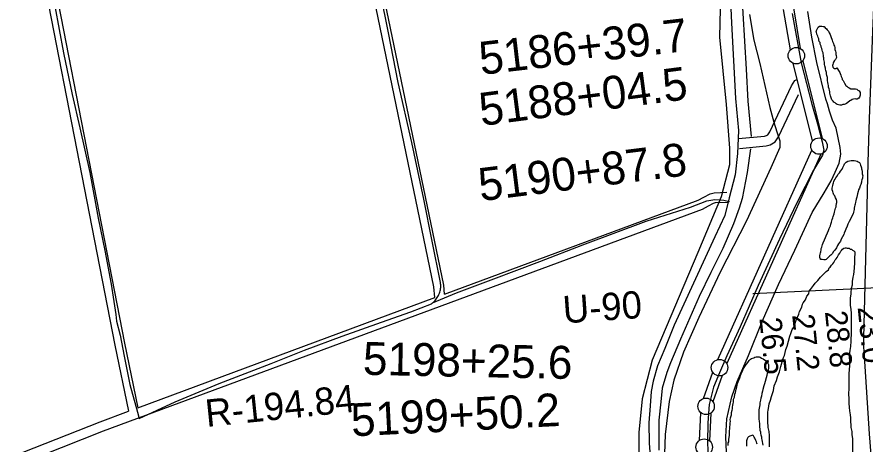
# Model space of a CAD drawing. Extents: x 3324125 to 3362000, y 600753 to 626151.
# Drawn here: x 3330131 to 3332706, y 616943 to 618241 of the extents above; entities that cross this region are included whole.
import ezdxf

# ---------------------------------------------------------------- set-up
doc = ezdxf.new("R2010")
doc.units = 0
for name, color, linetype in [('V-DTCH-CNTR', 7, 'Continuous'), ('V-FLOD-BASE', 7, 'Continuous'), ('V-LEVE-TOET', 7, 'Continuous'), ('V-RIVR-RANG', 7, 'Continuous'), ('V-RIVR-RANG-IDEN', 7, 'Continuous'), ('V-ROAD-CNTR', 7, 'Continuous'), ('V-SITE-VEGE', 7, 'Continuous'), ('V-SURV-IDEN', 7, 'Continuous'), ('V-SURV-LINE', 7, 'Continuous'), ('V-TOPO-MAJR', 7, 'Continuous'), ('V-TOPO-SHOR', 7, 'Continuous')]:
    doc.layers.add(name, color=color, linetype=linetype)

msp = doc.modelspace()

# ---------------------------------------------------------------- linework, layer by layer
at = {"layer": 'V-DTCH-CNTR'}
for points in [[(3330126.9, 618919.7), (3330132.5, 618888.2), (3330139.8, 618849.5), (3330156.8, 618763.4), (3330171.7, 618671.3), (3330189.8, 618572.8), (3330210.7, 618476.7), (3330226.4, 618377.8), (3330245.6, 618273.4), (3330271.8, 618131.8), (3330298.4, 618004.6), (3330321.7, 617904.1), (3330351.9, 617768.1), (3330376.9, 617628.9), (3330397.7, 617531.6), (3330416.6, 617429.1), (3330430.7, 617337.1), (3330433, 617316.3), (3330443.5, 617274), (3330455.8, 617210.2), (3330473.6, 617123.7), (3330496.5, 617039.5), (3330502, 617020.8)], [(3330502, 617020.8), (3330611.4, 617071.8), (3330744.8, 617126.7), (3330902.1, 617187.8), (3331003.5, 617227.8), (3331118.5, 617270.9), (3331237.5, 617313.1), (3331326.1, 617345.2), (3331389.2, 617369.5), (3331392.1, 617371.7), (3331394.9, 617374.1), (3331397.6, 617376.6), (3331400.1, 617379.3), (3331402.5, 617382.1), (3331404.8, 617385), (3331406.8, 617388), (3331408.7, 617391.2), (3331410.4, 617394.4), (3331412, 617397.8), (3331413.3, 617401.2), (3331414.5, 617404.7), (3331415.4, 617408.2), (3331416.2, 617411.8), (3331416.8, 617415.5), (3331417.2, 617419.1), (3331417.3, 617422.8), (3331417.3, 617426.5), (3331417, 617430.2), (3331416.6, 617433.8), (3331391.2, 617559.1), (3331366.5, 617686.7), (3331329.4, 617859.7), (3331288.4, 618041.6), (3331258.3, 618192.4), (3331234.4, 618313.6)], [(3331392.1, 617371.7), (3331464.8, 617402.3), (3331578.2, 617445.4), (3331717.9, 617497.8), (3331848.9, 617548.8), (3332041.3, 617620), (3332175.4, 617663), (3332225.7, 617682.5), (3332249.6, 617686.4), (3332277.5, 617683.8), (3332293.9, 617680.2)]]:
    msp.add_lwpolyline(points, dxfattribs=at)
at = {"layer": 'V-FLOD-BASE'}
msp.add_lwpolyline([(3332485, 618250.7), (3332512, 618101.1), (3332544.5, 617976), (3332561.6, 617915.8), (3332575.8, 617860.9), (3332580.3, 617836.3), (3332576.7, 617820.6), (3332549, 617774.7), (3332498.2, 617675.8), (3332446.1, 617565.8), (3332381, 617424.5), (3332326.5, 617298.8), (3332285.7, 617210.9), (3332264.3, 617159.1), (3332246, 617115.5), (3332232.8, 617063), (3332228.4, 617007.6), (3332227.4, 616947.5), (3332230.4, 616875.1)], dxfattribs=at)
at = {"layer": 'V-LEVE-TOET'}
for points in [[(3332355.4, 618248), (3332368.3, 618169.8), (3332386.5, 618099), (3332416.6, 617965.8), (3332428.6, 617920.8), (3332438.3, 617891.5), (3332446.9, 617864), (3332447.3, 617844.2), (3332419.5, 617781.9), (3332345.5, 617621.4), (3332265.7, 617464.9), (3332200.7, 617327.6), (3332155, 617221.7), (3332125.3, 617136.7), (3332110.9, 617072), (3332098.6, 616972.3), (3332097, 616912.8)], [(3332286, 616894.6), (3332282.9, 616965.2), (3332285.6, 617019.5), (3332301.2, 617086.5), (3332317.3, 617133.1), (3332352.2, 617212.2), (3332393.7, 617315.8), (3332442.9, 617428.1), (3332492.6, 617532.3), (3332545.3, 617646.3), (3332581.8, 617706.2), (3332602.5, 617742.8), (3332615.5, 617769), (3332626.8, 617796.4), (3332632.2, 617823.7), (3332630.6, 617844.2), (3332618.1, 617902.6), (3332606.6, 617926.6), (3332597.4, 617954.7), (3332591.8, 617976.9), (3332587.2, 617990.4), (3332559.9, 618102), (3332544.6, 618179.1), (3332532.3, 618256.8)]]:
    msp.add_lwpolyline(points, dxfattribs=at)
at = {"layer": 'V-RIVR-RANG'}
msp.add_line((3332364.6, 617400.2), (3333505.2, 617456.3), dxfattribs=at)
at = {"layer": 'V-ROAD-CNTR'}
for points in [[(3332435.8, 620389.6), (3332374.7, 619523.7), (3332301.3, 618552.7), (3332296.7, 618455.5), (3332294.2, 618354.6), (3332300.5, 618222.7), (3332312.6, 617992.5), (3332321.2, 617895.8), (3332318.6, 617826.1), (3332311.6, 617761.4), (3332293.4, 617690.8), (3332279.8, 617637.3), (3332250, 617572.9), (3332125.9, 617304.4), (3332097.6, 617233.7), (3332075.6, 617180.9), (3332062.2, 617134.3), (3332055.9, 617103.1), (3332053.1, 617059.6), (3332049, 617007.9), (3332050.3, 616945.8), (3332056, 616867)], [(3330111, 618871.3), (3330427.3, 617243.1), (3330469.2, 617043)], [(3330140.4, 618877), (3330456.7, 617249.1), (3330497.7, 617053.5)], [(3331399.7, 617387.8), (3331396.8, 617421), (3331161.7, 618557), (3331116.3, 618749.3)], [(3331428.8, 617398.6), (3331426.5, 617425.3), (3331220.1, 618422.6)], [(3332321.9, 617871), (3332400.7, 617878.7), (3332406.2, 617880), (3332410.9, 617883), (3332416.3, 617891.4), (3332482.7, 618031.4), (3332492.6, 618047.7), (3332498.7, 618050.4)], [(3332324.9, 617841.1), (3332405.7, 617849), (3332418, 617852), (3332432.6, 617861.1), (3332442.6, 617876.8), (3332503.3, 618004.8)], [(3331428.8, 617398.6), (3332199.2, 617684), (3332215.9, 617693.5), (3332235.5, 617703.7), (3332248.1, 617706.4), (3332286.4, 617708.2)], [(3329622.7, 616703.3), (3329633, 616708.7), (3329640.7, 616710), (3329667.1, 616715.1), (3329709.7, 616718.1), (3329737.4, 616721.6), (3329760, 616732.4), (3330393.7, 616983), (3332211.8, 617656.7), (3332230.2, 617667.1), (3332245.9, 617675.2), (3332252, 617676.6), (3332287.8, 617678.2)], [(3330497.7, 617053.5), (3331399.7, 617387.8)], [(3329608.8, 616729.9), (3329623.3, 616737.5), (3329635.4, 616739.5), (3329663.2, 616744.9), (3329706.7, 616747.9), (3329728.8, 616750.8), (3329748, 616759.9), (3330382.9, 617011), (3330469.2, 617043)]]:
    msp.add_lwpolyline(points, dxfattribs=at)
at = {"layer": 'V-SITE-VEGE'}
for points in [[(3332415.4, 616934.8), (3332415.6, 616969.1), (3332414.3, 616981.5), (3332411.7, 616993.8), (3332411.7, 616997.9), (3332410.4, 617007.6), (3332410.6, 617040.5), (3332412, 617044.6), (3332413.4, 617058.3), (3332414.9, 617065.1), (3332419, 617076.1), (3332421.9, 617087), (3332427.5, 617106.2), (3332430.3, 617119.9), (3332437.3, 617136.3), (3332440.1, 617147.3), (3332445.7, 617162.3), (3332449.9, 617178.8), (3332454.1, 617192.5), (3332458.3, 617206.1), (3332461.1, 617211.6), (3332465.3, 617230.8), (3332469.5, 617240.4), (3332473.7, 617255.4), (3332477.9, 617270.5), (3332480.7, 617278.7), (3332484.9, 617291), (3332489.1, 617297.8), (3332494.6, 617312.9), (3332497.4, 617322.5), (3332504.4, 617337.5), (3332507.2, 617345.7), (3332514.1, 617359.4), (3332515.6, 617367.6), (3332518.3, 617371.7), (3332525.3, 617381.3), (3332529.4, 617392.2), (3332535, 617399.1), (3332536.4, 617407.3), (3332540.6, 617412.7), (3332548.9, 617425), (3332554.4, 617431.8), (3332562.7, 617440), (3332571, 617449.6), (3332575.1, 617455), (3332587.5, 617467.3), (3332594.4, 617472.7), (3332597.2, 617478.2), (3332600, 617480.9), (3332604.1, 617486.4), (3332608.3, 617490.5), (3332611, 617494.6), (3332615.2, 617502.8), (3332618, 617505.5), (3332620.7, 617509.6), (3332624.9, 617517.8), (3332629.1, 617523.3), (3332631.8, 617528.7), (3332634.6, 617531.5), (3332637.4, 617535.6), (3332641.5, 617538.3), (3332645.6, 617539.6)], [(3332645.6, 617539.6), (3332648.4, 617539.6), (3332651.1, 617538.2), (3332658, 617538.2), (3332660.7, 617535.4), (3332664.8, 617535.4), (3332667.5, 617532.6), (3332671.6, 617529.9), (3332674.3, 617527.1), (3332674.2, 617503.8), (3332674.1, 617494.2), (3332672.7, 617477.7), (3332671.2, 617458.5), (3332668.4, 617450.3), (3332666.9, 617436.6), (3332666.8, 617425.6), (3332664, 617416.1), (3332662.6, 617403.7), (3332662.6, 617399.6), (3332661.1, 617385.9), (3332661, 617365.3), (3332662.2, 617351.6), (3332663.5, 617340.6), (3332663.2, 617283), (3332663, 617255.6), (3332661.5, 617239.1), (3332660.1, 617226.8), (3332657.2, 617211.7), (3332658.5, 617189.8), (3332658.4, 617181.5), (3332656.9, 617156.8), (3332656.6, 617121.2), (3332656.6, 617110.2), (3332655.1, 617097.9), (3332656.4, 617078.7), (3332656.3, 617067.7), (3332657.6, 617054), (3332658.9, 617044.4), (3332660.2, 617032), (3332661.5, 617022.4), (3332661.4, 617010.1), (3332662.7, 617001.8), (3332662.7, 616993.6), (3332665.3, 616981.2), (3332665.3, 616971.6), (3332667.9, 616959.3), (3332667.6, 616908.5)]]:
    msp.add_lwpolyline(points, dxfattribs=at)
at = {"layer": 'V-SURV-LINE'}
for points in [[(3332488.1, 618268.5), (3332508.7, 618145.3)], [(3332479.1, 618140.3), (3332458.5, 618263.5)], [(3332546.6, 617864), (3332487.5, 618100.1)], [(3332516.6, 618107.3), (3332575.7, 617871.3)], [(3332258.5, 617199.6), (3332544.2, 617836.2)], [(3332571.6, 617823.9), (3332285.9, 617187.3)], [(3332215.5, 617081.4), (3332243.3, 617161.3)], [(3332271.6, 617151.4), (3332243.8, 617071.5)], [(3332203.3, 616954.3), (3332207.2, 617038.3)], [(3332237.1, 617036.9), (3332233.3, 616953)]]:
    msp.add_lwpolyline(points, dxfattribs=at)
for centre in [(3332497.2, 618123.1), (3332566, 617848.3), (3332264, 617175.2), (3332223.1, 617057.6), (3332217.4, 616933.7)]:
    msp.add_circle(centre, 25, dxfattribs=at)
at = {"layer": 'V-TOPO-MAJR'}
msp.add_lwpolyline([(3333375.7, 620872.5), (3332686.5, 619553.9), (3332686, 619548.3), (3332738.3, 618427.5), (3332736.6, 618393.3), (3332728.3, 618196.5), (3332723.1, 618063.9), (3332718.3, 617931.3), (3332714.4, 617798.6), (3332710.9, 617666), (3332701.6, 617266), (3332701.4, 617252.2), (3332701.5, 617238.3), (3332702, 617224.4), (3332702.8, 617210.5), (3332718.4, 616974.5), (3332723, 616910.5)], dxfattribs=at)
at = {"layer": 'V-TOPO-SHOR'}
for points in [[(3332361.2, 617877.9), (3332351, 617985.2), (3332345.9, 618082.4), (3332330.5, 618338.1), (3332335.6, 618563.1), (3332356.1, 618736.9), (3332371.4, 619018.2)], [(3332315.2, 618946.6), (3332274.3, 618588.6), (3332269.2, 618394.3), (3332264.1, 618179.6), (3332284.5, 617975), (3332294.7, 617842.1), (3332294.7, 617790.9), (3332269.2, 617693.8), (3332197.6, 617525), (3332059.5, 617197.8), (3332028.8, 617080.2), (3332018.6, 616977.9), (3332018.6, 616896.1)], [(3332621.9, 618082.8), (3332625.1, 618078), (3332627.4, 618074.8), (3332629, 618071.6), (3332630.6, 618068.5), (3332632.1, 618063.7), (3332633.7, 618059.7), (3332636.1, 618054.1), (3332636.8, 618050.9), (3332639.2, 618047.7), (3332641.6, 618043.7), (3332643.9, 618039.7), (3332647.9, 618032.5), (3332650.2, 618030.1), (3332653.4, 618027.7), (3332657.4, 618025.3), (3332662.9, 618022.8), (3332666.1, 618022), (3332669.3, 618022), (3332673.3, 618022), (3332676.5, 618022), (3332680.5, 618021.1), (3332684.4, 618018.7), (3332687.6, 618016.3), (3332690.7, 618011.5), (3332690.7, 618007.5), (3332690.7, 618003.5), (3332689.9, 618000.4), (3332689.1, 617997.2), (3332686.7, 617994), (3332681.9, 617990.9), (3332678.7, 617990.9), (3332675.5, 617991.7), (3332670.7, 617990.9), (3332666.7, 617989.4), (3332662.7, 617987), (3332659.5, 617985.4), (3332653.9, 617980.7), (3332649.9, 617977.5), (3332645.9, 617976), (3332642.7, 617975.2), (3332638.7, 617974.4), (3332633.9, 617972.8), (3332629.2, 617972.9), (3332625.2, 617973.7), (3332621.2, 617974.5), (3332618, 617976.9), (3332614.9, 617979.3), (3332610.9, 617981.8), (3332608.5, 617985), (3332605.4, 617989), (3332603, 617995.3), (3332600.7, 618000.9), (3332599.9, 618004.9), (3332599.1, 618008.9), (3332599.2, 618012.9), (3332597.6, 618018.5), (3332596.8, 618022.5), (3332595.3, 618027.3), (3332595.3, 618032), (3332593.7, 618036.8), (3332593, 618041.6), (3332592.2, 618048), (3332592.2, 618052), (3332591.5, 618056.8), (3332589.9, 618063.1), (3332589.2, 618067.9), (3332588.4, 618071.9), (3332586.8, 618078.3), (3332586.1, 618082.3), (3332586.1, 618085.5), (3332583.7, 618091.9), (3332583, 618095.8), (3332582.2, 618103), (3332581.4, 618107.8), (3332580.7, 618111.8), (3332580.7, 618116.6), (3332579.9, 618119.8), (3332579.2, 618124.5), (3332578.4, 618128.5), (3332578.4, 618131.7), (3332576.8, 618135.7), (3332575.3, 618139.7), (3332574.5, 618144.5), (3332573, 618148.5), (3332572.2, 618151.7), (3332569.8, 618158.1), (3332569.1, 618162.8), (3332566.7, 618166), (3332565.9, 618170.8), (3332565.1, 618174), (3332563.6, 618178), (3332562.8, 618182.8), (3332559.7, 618188.4), (3332558.1, 618194.8), (3332557.3, 618198), (3332559, 618201.9), (3332561.4, 618205.9), (3332563.8, 618209.9), (3332567.8, 618212.2), (3332571, 618213)], [(3332571, 618213), (3332575, 618212.2), (3332578.9, 618211.4), (3332582.1, 618211.3), (3332584.5, 618208.1), (3332588.4, 618204.9), (3332590.8, 618201.7), (3332594.8, 618197.7), (3332597.1, 618192.1), (3332599.5, 618187.3), (3332601.1, 618184.1), (3332603.4, 618177.8), (3332605, 618173), (3332605.7, 618169.8), (3332607.3, 618166.6), (3332609.7, 618160.2), (3332611.2, 618155.4), (3332612.8, 618152.2), (3332613.6, 618148.2), (3332614.3, 618145), (3332614.3, 618141.8), (3332615.9, 618137), (3332617.5, 618132.3), (3332617.4, 618126.7), (3332618.2, 618123.5), (3332618.9, 618117.1), (3332615.7, 618111.6), (3332613.3, 618108.4), (3332610.1, 618103.6), (3332608.5, 618100.5), (3332607.7, 618096.5), (3332606.8, 618093.3), (3332607.6, 618088.5), (3332610, 618086.1), (3332613.2, 618084.5), (3332617.1, 618084.5), (3332620.3, 618086), (3332621.9, 618082.8)], [(3332358, 617839.8), (3332347.6, 617767.8), (3332332.3, 617689.4), (3332323.4, 617660), (3332305.9, 617612.3), (3332273.6, 617537.2), (3332237.3, 617464.2), (3332202.5, 617391.5), (3332145.5, 617261.7), (3332114.8, 617190.2), (3332103.5, 617160.8), (3332089.6, 617112.7), (3332085.4, 617071.3), (3332079.8, 617015.2), (3332079.2, 616924)], [(3332657.9, 617619), (3332653.9, 617611.1), (3332651.5, 617605.5), (3332647.4, 617596), (3332645.8, 617590.4), (3332642.6, 617584.1), (3332641, 617579.3), (3332636.9, 617572.2), (3332633.7, 617565.8), (3332631.3, 617559.5), (3332625.6, 617551.5), (3332622.4, 617546), (3332619.2, 617539.6), (3332614.4, 617531.7), (3332610.4, 617527.7), (3332605.5, 617521.4), (3332601.5, 617517.4), (3332599.1, 617515.1), (3332595.1, 617511.1), (3332592.7, 617508.7), (3332590.3, 617506.4), (3332587.9, 617504), (3332584.7, 617502.4), (3332580.7, 617502.4), (3332575.2, 617503.3), (3332572, 617504.1), (3332569.6, 617506.5), (3332568.8, 617509.7), (3332568.9, 617514.5), (3332569.7, 617520), (3332570.5, 617524), (3332571.3, 617527.2), (3332572.2, 617532.8), (3332573, 617537.5), (3332574.6, 617541.5), (3332577, 617549.5), (3332578.7, 617554.2), (3332582.7, 617563.8), (3332585.9, 617570.1), (3332587.6, 617575.7), (3332591.6, 617585.2), (3332594.8, 617591.6), (3332596.5, 617597.9), (3332600.5, 617605.9), (3332602.1, 617611.4), (3332603.8, 617617), (3332606.2, 617624.9), (3332607.8, 617630.5), (3332609.5, 617634.5), (3332611.9, 617642.4), (3332612.7, 617647.2), (3332614.4, 617652), (3332616, 617659.9), (3332617.6, 617663.9), (3332618.4, 617667.1), (3332619.3, 617673.4), (3332620.1, 617677.4), (3332620.1, 617681.4), (3332619.3, 617686.2), (3332616.2, 617691), (3332615.4, 617694.2), (3332613.8, 617697.4), (3332611.5, 617700.6), (3332609.1, 617706.2), (3332607.6, 617710.2), (3332606, 617715.7), (3332606, 617720.5), (3332606.9, 617724.5), (3332607.7, 617728.5), (3332608.5, 617733.3), (3332610.1, 617736.4), (3332610.9, 617740.4), (3332611.8, 617743.6), (3332615, 617748.3), (3332617.4, 617751.5), (3332619.8, 617756.3), (3332624.6, 617762.6), (3332627.8, 617766.6), (3332631.1, 617772.1), (3332635.9, 617778.5), (3332638.3, 617783.2), (3332639.9, 617787.2), (3332642.3, 617791.2), (3332643.9, 617794.4), (3332646.4, 617797.5), (3332648.8, 617799.9), (3332653.6, 617802.3), (3332658.3, 617803.8), (3332663.9, 617804.6), (3332668.7, 617804.6), (3332672.7, 617804.5), (3332678.3, 617803.7), (3332682.2, 617802.1), (3332685.4, 617800.5), (3332688.6, 617798.1), (3332690.9, 617794.1), (3332691.7, 617790.1), (3332694.1, 617785.3), (3332694.8, 617782.1), (3332694.8, 617778.9), (3332695.6, 617775.7)], [(3332695.6, 617775.7), (3332697.2, 617770.9), (3332697.1, 617766.9), (3332697.1, 617763.7), (3332698.7, 617758.2), (3332697.8, 617754.2), (3332697.8, 617751), (3332696.2, 617745.4), (3332695.4, 617741.5), (3332694.6, 617738.3), (3332692.9, 617731.9), (3332691.3, 617727.9), (3332688.9, 617720), (3332686.4, 617715.2), (3332684.8, 617710.5), (3332683.2, 617703.3), (3332681.6, 617697.7), (3332680.7, 617693), (3332679.1, 617686.6), (3332677.5, 617681.8), (3332676.6, 617677.9), (3332675.8, 617672.3), (3332675, 617669.1), (3332674.2, 617665.1), (3332672.5, 617659.6), (3332672.5, 617655.6), (3332671.7, 617651.6), (3332670.9, 617647.6), (3332669.3, 617642.9), (3332657.9, 617619)], [(3332289.7, 616938.3), (3332289.7, 616943.8), (3332290.5, 616947), (3332292.1, 616950.2), (3332292.2, 616958.2), (3332293, 616962.9), (3332293.9, 616970.1), (3332293.9, 616974.1), (3332294.7, 616978.1), (3332294.7, 616982.8), (3332295.6, 616989.2), (3332295.6, 616992.4), (3332295.6, 616995.6), (3332296.4, 617001.1), (3332296.5, 617006.7), (3332297.3, 617012.3), (3332296.5, 617016.3), (3332297.4, 617022.6), (3332298.2, 617025.8), (3332299.8, 617032.2), (3332299.9, 617038.6), (3332302.3, 617045.7), (3332303.1, 617049.7), (3332303.2, 617055.3), (3332304.8, 617061.6), (3332305.6, 617066.4), (3332306.4, 617070.4), (3332306.5, 617076), (3332306.5, 617079.9), (3332308.9, 617085.5), (3332310.6, 617094.2), (3332312.2, 617099.8), (3332314.7, 617110.2), (3332316.3, 617117.3), (3332318.8, 617126.9), (3332322.8, 617137.2), (3332325.2, 617144.3), (3332327.7, 617151.5), (3332331.7, 617161.8), (3332334.2, 617166.6), (3332335.8, 617170.6), (3332339, 617176.1), (3332343, 617181.7), (3332345.4, 617185.6), (3332349.4, 617190.4), (3332351.9, 617194.3), (3332354.3, 617196.7), (3332358.3, 617200.7), (3332360.7, 617203), (3332367.9, 617205.4), (3332371.1, 617207), (3332375, 617207.7), (3332378.2, 617208.5), (3332383.8, 617207.7), (3332387, 617206.9), (3332391.7, 617204.4), (3332396.5, 617202), (3332403.6, 617196.4), (3332406.8, 617192.4), (3332410.8, 617189.2), (3332412.3, 617184.4), (3332413.1, 617180.4), (3332412.3, 617173.2), (3332411.4, 617167.7), (3332411.4, 617162.1), (3332408.2, 617158.1), (3332407.3, 617151), (3332405.7, 617144.6), (3332402.4, 617133.5), (3332400.8, 617126.3), (3332398.4, 617120), (3332395.9, 617108.8), (3332394.3, 617103.3), (3332392.6, 617096.9), (3332391, 617088.2), (3332389.4, 617082.6), (3332388.5, 617076.2), (3332386.1, 617068.3), (3332386, 617061.9), (3332385.2, 617057.1), (3332383.6, 617046.8), (3332383.5, 617040.4), (3332383.5, 617034), (3332383.4, 617024.5), (3332383.4, 617018.9), (3332384.1, 617012.5), (3332384.9, 617004.6), (3332384.9, 617000.6), (3332385.6, 616994.2), (3332386.4, 616989.4), (3332386.4, 616985.4), (3332387.9, 616979.8), (3332388.7, 616975.1), (3332389.4, 616971.1), (3332391, 616964.7), (3332391.8, 616959.9)], [(3332378.1, 616942.5), (3332377.3, 616945.7), (3332375.8, 616949.7), (3332374.2, 616953.6), (3332371.1, 616960.8), (3332369.5, 616964), (3332367.1, 616968), (3332364.7, 616970.4), (3332359.2, 616968.1), (3332356, 616966.5), (3332352, 616964.9), (3332349.6, 616962.6), (3332347.9, 616958.6), (3332346.3, 616953), (3332345.5, 616949.1), (3332345.5, 616945.9), (3332345.4, 616937.1)], [(3332391.8, 616959.9), (3332392.5, 616955.9), (3332393.3, 616950.3), (3332394.8, 616944.8), (3332395.6, 616939.2)]]:
    msp.add_lwpolyline(points, dxfattribs=at)

# ---------------------------------------------------------------- texts
at = {"layer": 'V-RIVR-RANG'}
for s, p in [('28.8', (3332583.9, 617345.6)), ('23.0', (3332683.1, 617358.8)), ('26.5', (3332384.9, 617325.1)), ('27.2', (3332484.4, 617335.4))]:
    msp.add_text(s, height=67, rotation=275.7383, dxfattribs=at).set_placement(p)
at = {"layer": 'V-RIVR-RANG-IDEN'}
for s, rotation, p in [('U-90', 4.0204, (3331790.9, 617309.5)), ('R-194.84', 5.8813, (3330706.6, 616994.8))]:
    msp.add_text(s, height=83, rotation=rotation, dxfattribs=at).set_placement(p)
at = {"layer": 'V-SURV-IDEN'}
for s, rotation, p in [('5186+39.7', 6.635, (3331539.6, 618064.5)), ('5188+04.5', 7.3961, (3331540.6, 617909.4)), ('5190+87.8', 7.1608, (3331538.2, 617680.8)), ('5198+25.6', 358.8425, (3331180.4, 617153.5)), ('5199+50.2', 2.8821, (3331147.3, 616966.2))]:
    msp.add_text(s, height=100, rotation=rotation, dxfattribs=at).set_placement(p)

doc.saveas('drawing.dxf')
